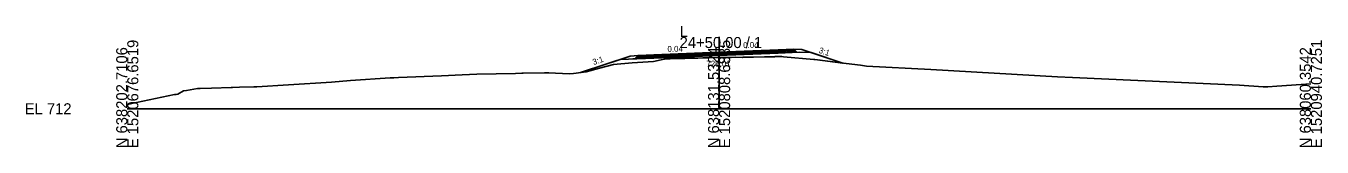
# Model space of a CAD drawing. Extents: x -26 to 3903, y -10 to 9531.
# Drawn here: x 974.3 to 1302.8, y 4490.3 to 4521 of the extents above; entities that cross this region are included whole.
import ezdxf

# ---------------------------------------------------------------- set-up
doc = ezdxf.new("R2010")
doc.units = 0
for name, color, linetype in [('Default', 7, 'Continuous'), ('Exist Cross Section Cell', 7, 'Continuous'), ('Exist XS Center Line Elevation Label', 7, 'Continuous'), ('Exist XS Ground Line', 7, 'Continuous'), ('Prop CMT Pvmt Course 1', 7, 'Continuous'), ('Prop CMT Pvmt Course 2', 7, 'Continuous'), ('Prop CMT Pvmt Course 3', 7, 'Continuous'), ('Prop CMT Pvmt Surface', 7, 'Continuous'), ('Prop CMT Pvmt Surface Shoulder', 7, 'Continuous'), ('Prop CMT Shld Paved Course 1', 7, 'Continuous'), ('Prop CMT Shld Paved Course 2', 7, 'Continuous'), ('Prop CMT Shld Paved Course 3', 7, 'Continuous'), ('Prop CMT Slope Grass', 7, 'Continuous'), ('Prop CMT Subgrade Earthwork', 7, 'Continuous'), ('Prop XS Earthwork Shape', 7, 'Continuous'), ('Prop XS SE Text', 7, 'Continuous'), ('Prop XS Side Slope Text', 7, 'Continuous')]:
    doc.layers.add(name, color=color, linetype=linetype)

msp = doc.modelspace()

# ---------------------------------------------------------------- linework, layer by layer
at = {"layer": 'Exist Cross Section Cell'}
for p, q in [((1150, 4500), (1150, 4518.18)), ((1000, 4500), (1150, 4500)), ((1150, 4500), (1300, 4500))]:
    msp.add_line(p, q, dxfattribs=at)
at = {"layer": 'Exist XS Ground Line'}
msp.add_lwpolyline([(1000, 4501.06), (1000.03, 4501.07), (1000.74, 4501.22), (1011.93, 4503.6), (1012.37, 4503.63), (1012.83, 4503.71), (1014.23, 4504.58), (1014.97, 4504.65), (1017.77, 4505.13), (1018.49, 4505.15), (1021.31, 4505.22), (1026.31, 4505.4), (1026.41, 4505.41), (1026.66, 4505.42), (1028.45, 4505.48), (1032.08, 4505.55), (1032.87, 4505.6), (1040.84, 4506.05), (1051.78, 4506.78), (1056.61, 4507.17), (1066.64, 4507.81), (1067.22, 4507.84), (1067.52, 4507.86), (1068.71, 4507.91), (1079.63, 4508.36), (1084.86, 4508.62), (1088.62, 4508.77), (1098.42, 4508.97), (1100.04, 4509), (1100.19, 4509.01), (1100.34, 4509.01), (1105.78, 4509.12), (1106.19, 4509.11), (1106.82, 4509.08), (1112.03, 4508.83), (1113.09, 4508.92), (1116.34, 4509.35), (1119.69, 4510.26), (1123.21, 4511.24), (1127.94, 4511.62), (1133.36, 4512.01), (1136.06, 4512.59), (1136.19, 4512.62), (1136.31, 4512.63), (1136.44, 4512.64), (1137.3, 4512.69), (1137.56, 4512.69), (1138.9, 4512.7), (1140.66, 4512.75), (1141.36, 4512.77), (1141.74, 4512.78), (1143.02, 4512.81), (1144.59, 4512.85), (1145.92, 4512.89), (1147.42, 4512.93), (1149.72, 4513.01), (1149.86, 4513.01), (1150.02, 4513.01), (1151.16, 4513.02), (1153.08, 4513.02), (1154.25, 4513.03), (1155.92, 4513.02), (1156.09, 4513.03), (1156.43, 4513.03), (1158.75, 4513.06), (1161.48, 4513.12), (1161.59, 4513.12), (1161.63, 4513.12), (1161.69, 4513.12), (1164.05, 4513.19), (1164.24, 4513.2), (1164.73, 4513.2), (1165.2, 4513.2), (1165.92, 4513.2), (1166.32, 4513.19), (1173.99, 4512.49), (1174.11, 4512.48), (1174.25, 4512.46), (1182.23, 4511.48), (1185.83, 4511.01), (1187.35, 4510.79), (1203.69, 4509.91), (1235.81, 4508.07), (1239.6, 4507.95), (1281.89, 4506.02), (1287.93, 4505.58), (1289.07, 4505.59), (1291.37, 4505.75), (1300, 4506.31)], dxfattribs=at)
at = {"layer": 'Prop CMT Pvmt Course 1'}
for points in [[(1149.97, 4514.33), (1133.49, 4513.67)], [(1133.49, 4513.42), (1149.97, 4514.08)], [(1149.97, 4514.33), (1164.97, 4514.93)], [(1164.97, 4514.68), (1149.97, 4514.08)], [(1149.97, 4514.08), (1149.97, 4514.33)], [(1149.97, 4514.08), (1149.97, 4514.33)], [(1164.97, 4514.93), (1164.97, 4514.68)], [(1133.49, 4513.67), (1133.49, 4513.42)]]:
    msp.add_lwpolyline(points, dxfattribs=at)
msp.add_lwpolyline([(1149.97, 4514.08), (1149.97, 4514.21), (1149.97, 4514.21), (1149.97, 4514.08)], close=True, dxfattribs=at)
msp.add_lwpolyline([(1149.97, 4514.08), (1149.97, 4514.21), (1149.97, 4514.21), (1149.97, 4514.08)], close=True, dxfattribs=at)
at = {"layer": 'Prop CMT Pvmt Course 2'}
for points in [[(1149.97, 4514.08), (1133.49, 4513.42)], [(1149.97, 4514.08), (1164.97, 4514.68)], [(1164.97, 4514.35), (1149.97, 4513.75)], [(1149.97, 4513.75), (1149.97, 4514.08)], [(1149.97, 4513.75), (1149.97, 4514.08)], [(1164.97, 4514.68), (1164.97, 4514.35)], [(1133.49, 4513.09), (1149.97, 4513.75)], [(1133.49, 4513.42), (1133.49, 4513.09)]]:
    msp.add_lwpolyline(points, dxfattribs=at)
at = {"layer": 'Prop CMT Pvmt Course 3'}
for points in [[(1149.97, 4513.75), (1164.97, 4514.35)], [(1164.97, 4514.1), (1149.97, 4513.5)], [(1164.97, 4514.35), (1164.97, 4514.1)], [(1149.97, 4513.75), (1133.49, 4513.09)], [(1133.49, 4512.84), (1149.97, 4513.5)], [(1133.49, 4513.09), (1133.49, 4512.84)], [(1149.97, 4513.5), (1149.97, 4513.75)], [(1149.97, 4513.5), (1149.97, 4513.75)]]:
    msp.add_lwpolyline(points, dxfattribs=at)
at = {"layer": 'Prop CMT Pvmt Surface'}
for points in [[(1149.97, 4514.33), (1133.49, 4513.67)], [(1149.97, 4514.33), (1164.97, 4514.93)]]:
    msp.add_lwpolyline(points, dxfattribs=at)
at = {"layer": 'Prop CMT Pvmt Surface Shoulder'}
for points in [[(1164.97, 4514.93), (1168.97, 4515.09)], [(1133.49, 4513.67), (1129.49, 4513.51)]]:
    msp.add_lwpolyline(points, dxfattribs=at)
at = {"layer": 'Prop CMT Shld Paved Course 1'}
for points in [[(1164.97, 4514.93), (1168.97, 4515.09), (1169.21, 4514.85)], [(1164.97, 4514.68), (1164.97, 4514.93)], [(1169.21, 4514.85), (1164.97, 4514.68)], [(1133.49, 4513.67), (1129.49, 4513.51), (1129.23, 4513.25)], [(1129.23, 4513.25), (1133.49, 4513.42)], [(1133.49, 4513.42), (1133.49, 4513.67)]]:
    msp.add_lwpolyline(points, dxfattribs=at)
at = {"layer": 'Prop CMT Shld Paved Course 2'}
for points in [[(1164.97, 4514.68), (1169.21, 4514.85), (1169.53, 4514.53)], [(1164.97, 4514.35), (1164.97, 4514.68)], [(1169.53, 4514.53), (1164.97, 4514.35)], [(1133.49, 4513.42), (1129.23, 4513.25), (1128.88, 4512.91)], [(1128.88, 4512.91), (1133.49, 4513.09)], [(1133.49, 4513.09), (1133.49, 4513.42)]]:
    msp.add_lwpolyline(points, dxfattribs=at)
at = {"layer": 'Prop CMT Shld Paved Course 3'}
for points in [[(1164.97, 4514.35), (1169.53, 4514.53), (1169.77, 4514.29)], [(1164.97, 4514.1), (1164.97, 4514.35)], [(1170.27, 4514.31), (1164.97, 4514.1)], [(1128.12, 4512.63), (1133.49, 4512.84)], [(1133.49, 4513.09), (1128.88, 4512.91), (1128.62, 4512.65)], [(1133.49, 4512.84), (1133.49, 4513.09)]]:
    msp.add_lwpolyline(points, dxfattribs=at)
at = {"layer": 'Prop CMT Slope Grass'}
for points in [[(1168.97, 4515.09), (1170.97, 4515.05), (1181.35, 4511.59)], [(1129.49, 4513.51), (1127.49, 4513.35), (1114.91, 4509.16)]]:
    msp.add_lwpolyline(points, dxfattribs=at)
at = {"layer": 'Prop CMT Subgrade Earthwork'}
for points in [[(1149.97, 4513.5), (1164.97, 4514.1)], [(1164.97, 4514.1), (1170.27, 4514.31)], [(1170.27, 4514.31), (1173.38, 4514.25)], [(1133.49, 4512.84), (1124.92, 4512.5)], [(1149.97, 4513.5), (1133.49, 4512.84)]]:
    msp.add_lwpolyline(points, dxfattribs=at)
at = {"layer": 'Prop XS Earthwork Shape'}
for points in [[(1164.73, 4513.2), (1165.2, 4513.2), (1165.92, 4513.2), (1166.32, 4513.19), (1173.99, 4512.49), (1174.25, 4512.46), (1181.35, 4511.59), (1173.38, 4514.25), (1170.27, 4514.31), (1164.97, 4514.1), (1149.97, 4513.5), (1133.49, 4512.84), (1124.92, 4512.5), (1114.91, 4509.16), (1116.34, 4509.35), (1119.69, 4510.26), (1123.21, 4511.24), (1127.94, 4511.62), (1133.36, 4512.01), (1136.06, 4512.59), (1136.31, 4512.63), (1136.44, 4512.64), (1137.3, 4512.69), (1137.56, 4512.69), (1138.9, 4512.7), (1140.66, 4512.75), (1141.36, 4512.77), (1141.74, 4512.78), (1143.02, 4512.81), (1144.59, 4512.85), (1145.92, 4512.89), (1147.42, 4512.93), (1149.72, 4513.01), (1149.86, 4513.01), (1150.02, 4513.01), (1151.16, 4513.02), (1153.08, 4513.02), (1154.25, 4513.03), (1155.92, 4513.02), (1156.09, 4513.03), (1156.43, 4513.03), (1158.75, 4513.06), (1161.48, 4513.12), (1161.69, 4513.12), (1164.05, 4513.19), (1164.24, 4513.2)], [(1149.97, 4513.5), (1133.49, 4512.84), (1124.92, 4512.5), (1114.91, 4509.16), (1116.34, 4509.35), (1119.69, 4510.26), (1123.21, 4511.24), (1127.94, 4511.62), (1133.36, 4512.01), (1136.06, 4512.59), (1136.31, 4512.63), (1136.44, 4512.64), (1137.3, 4512.69), (1137.56, 4512.69), (1138.9, 4512.7), (1140.66, 4512.75), (1141.36, 4512.77), (1141.74, 4512.78), (1143.02, 4512.81), (1144.59, 4512.85), (1145.92, 4512.89), (1147.42, 4512.93), (1149.72, 4513.01), (1149.86, 4513.01), (1150.02, 4513.01), (1151.16, 4513.02), (1153.08, 4513.02), (1154.25, 4513.03), (1155.92, 4513.02), (1156.09, 4513.03), (1156.43, 4513.03), (1158.75, 4513.06), (1161.48, 4513.12), (1161.69, 4513.12), (1164.05, 4513.19), (1164.24, 4513.2), (1164.73, 4513.2), (1165.2, 4513.2), (1165.92, 4513.2), (1166.32, 4513.19), (1173.99, 4512.49), (1174.25, 4512.46), (1181.35, 4511.59), (1173.38, 4514.25), (1170.27, 4514.31), (1164.97, 4514.1)]]:
    msp.add_lwpolyline(points, close=True, dxfattribs=at)

# ---------------------------------------------------------------- texts
at = {"layer": 'Default'}
msp.add_text('-', height=0.0001, dxfattribs=at).set_placement((1000, 4500))
at = {"layer": 'Exist Cross Section Cell'}
for s, p in [('L', (1140, 4518.18)), ('24+50.00 / 1', (1140, 4515.38)), ('EL 712', (974, 4498.6))]:
    msp.add_text(s, height=2.8, dxfattribs=at).set_placement(p)
for s, p in [('E 1520808.6885', (1152.8, 4490)), ('N 638202.7106', (1000, 4490)), ('E 1520676.6519', (1002.8, 4490)), ('N 638131.5324', (1150, 4490)), ('N 638060.3542', (1300, 4490)), ('E 1520940.7251', (1302.8, 4490))]:
    msp.add_text(s, height=2.8, rotation=90, dxfattribs=at).set_placement(p)
at = {"layer": 'Exist XS Center Line Elevation Label'}
msp.add_text('725.01', height=1.5, rotation=0.8401, dxfattribs=at).set_placement((1146.78, 4510.65))
at = {"layer": 'Prop XS SE Text'}
for p in [(1136.93, 4514.38), (1156.12, 4515.37)]:
    msp.add_text('0.04', height=1.5, rotation=1.1458, dxfattribs=at).set_placement(p)
at = {"layer": 'Prop XS Side Slope Text'}
for rotation, p in [(341.5668, (1175.12, 4514.22)), (18.4332, (1118.21, 4511.06))]:
    msp.add_text('3:1', height=1.5, rotation=rotation, dxfattribs=at).set_placement(p)

doc.saveas('drawing.dxf')
